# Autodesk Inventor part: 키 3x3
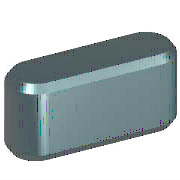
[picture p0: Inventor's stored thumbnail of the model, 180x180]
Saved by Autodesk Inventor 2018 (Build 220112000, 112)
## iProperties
Created: 2012-02
Part Number: 키 3x3
Material: 강철, 연강
Description: 키 및 해당 키홈
Document SubType Name: Modeling
Standard: KS B 1311
Designer: mduedu
Standards Organization: KS
Language: ko-KR
Size Designation: 3 x 3 x 12
Categories: <MemberInstance><Categories><Category DisplayName="샤프트 부품" InternalName="7f7aeb1f-a693-4053-b835-cee3144e0d98" Mnemonic="SHFT"><Category DisplayName="키" Interna
Density: 7.86 g/cm^3
Mass: 0.790122 g
Surface Area: 1.42216 cm^2
Volume: 0.100524 cm^3
Appearance: 노란색
IsCustomPart: 1
Author: mduedu
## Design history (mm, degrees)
workplane "Work Plane1"
workplane "Work Plane2"
sketch "스케치1"
  geometry: L1 (1.5, 1.5)-(10.5, 1.5); L2 (10.5, -1.5)-(1.5, -1.5); L3 (0, 9.4)-(0, -7.4) reference; L4 (-5, 0)-(30, 0) reference; L5 (12, 0)-(12, 7); A1 r 1.5 centre (1.5, 0) between (1.5, 1.5) and (1.5, -1.5); A2 r 1.5 centre (10.5, 0) between (10.5, -1.5) and (10.5, 1.5)
  constraints: 6 end point, 5 point on circle, 4 tangent, 3 point on line, 2 centre point, 1 horizontal, 1 parallel, 1 perpendicular
  dimensions: "d0" = 1.5 radius of A1 (= 0.5 x PB); "d13" = 1.5 radius of A2 (= 0.5 x PB); "d14" = 12 distance between parallel lines of L5 L3 (= NLG)
extrude "본체1" new body sketch "스케치1" taper "d3" = 0 deg; stored distance "d4" = 10
workplane "Work Plane3"
body "Solid1"
chamfer "모따기1" distance "d8" = 0.25 (= PHH); stored, may be unused: second distance "d9" = 0.25 (= PHH), angle "d15" = 45 deg
other parameters: "d1" = -1.8 (= -PNT), "d2" = 1.2 (= PH - PNT), "NLG" = 12 [user parameter; used in 3 equation terms], "PB" = 3 [user parameter; used in 2 equation terms], "PNT" = 1.8 [user parameter; used in 2 equation terms], "PH" = 3 [user parameter; used in 1 equation term], "PHH" = 0.25 [user parameter; used in 2 equation terms], "d10" = 0, "d16" = 0, "d17" = 0, "d18" = 0, "WDMIN" = 8 [user parameter], "PLB2" = 12 (= NLG) [user parameter], "PLB1" = 12 (= NLG) [user parameter], "RR" = 0.08 [user parameter], "PUEB" = 1.4 [user parameter]
